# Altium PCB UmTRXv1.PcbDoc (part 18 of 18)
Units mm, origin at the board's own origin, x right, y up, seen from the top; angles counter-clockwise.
Board outline 172 x 113 mm, 6 copper layers (Top Layer, GND, MidLayer1, Mid-Layer 2, InternalPlane2, Bottom Layer); 766 components, 613 nets, 3008 pads, 1360 vias.
Unrouted connection lines stored in the file: 2.
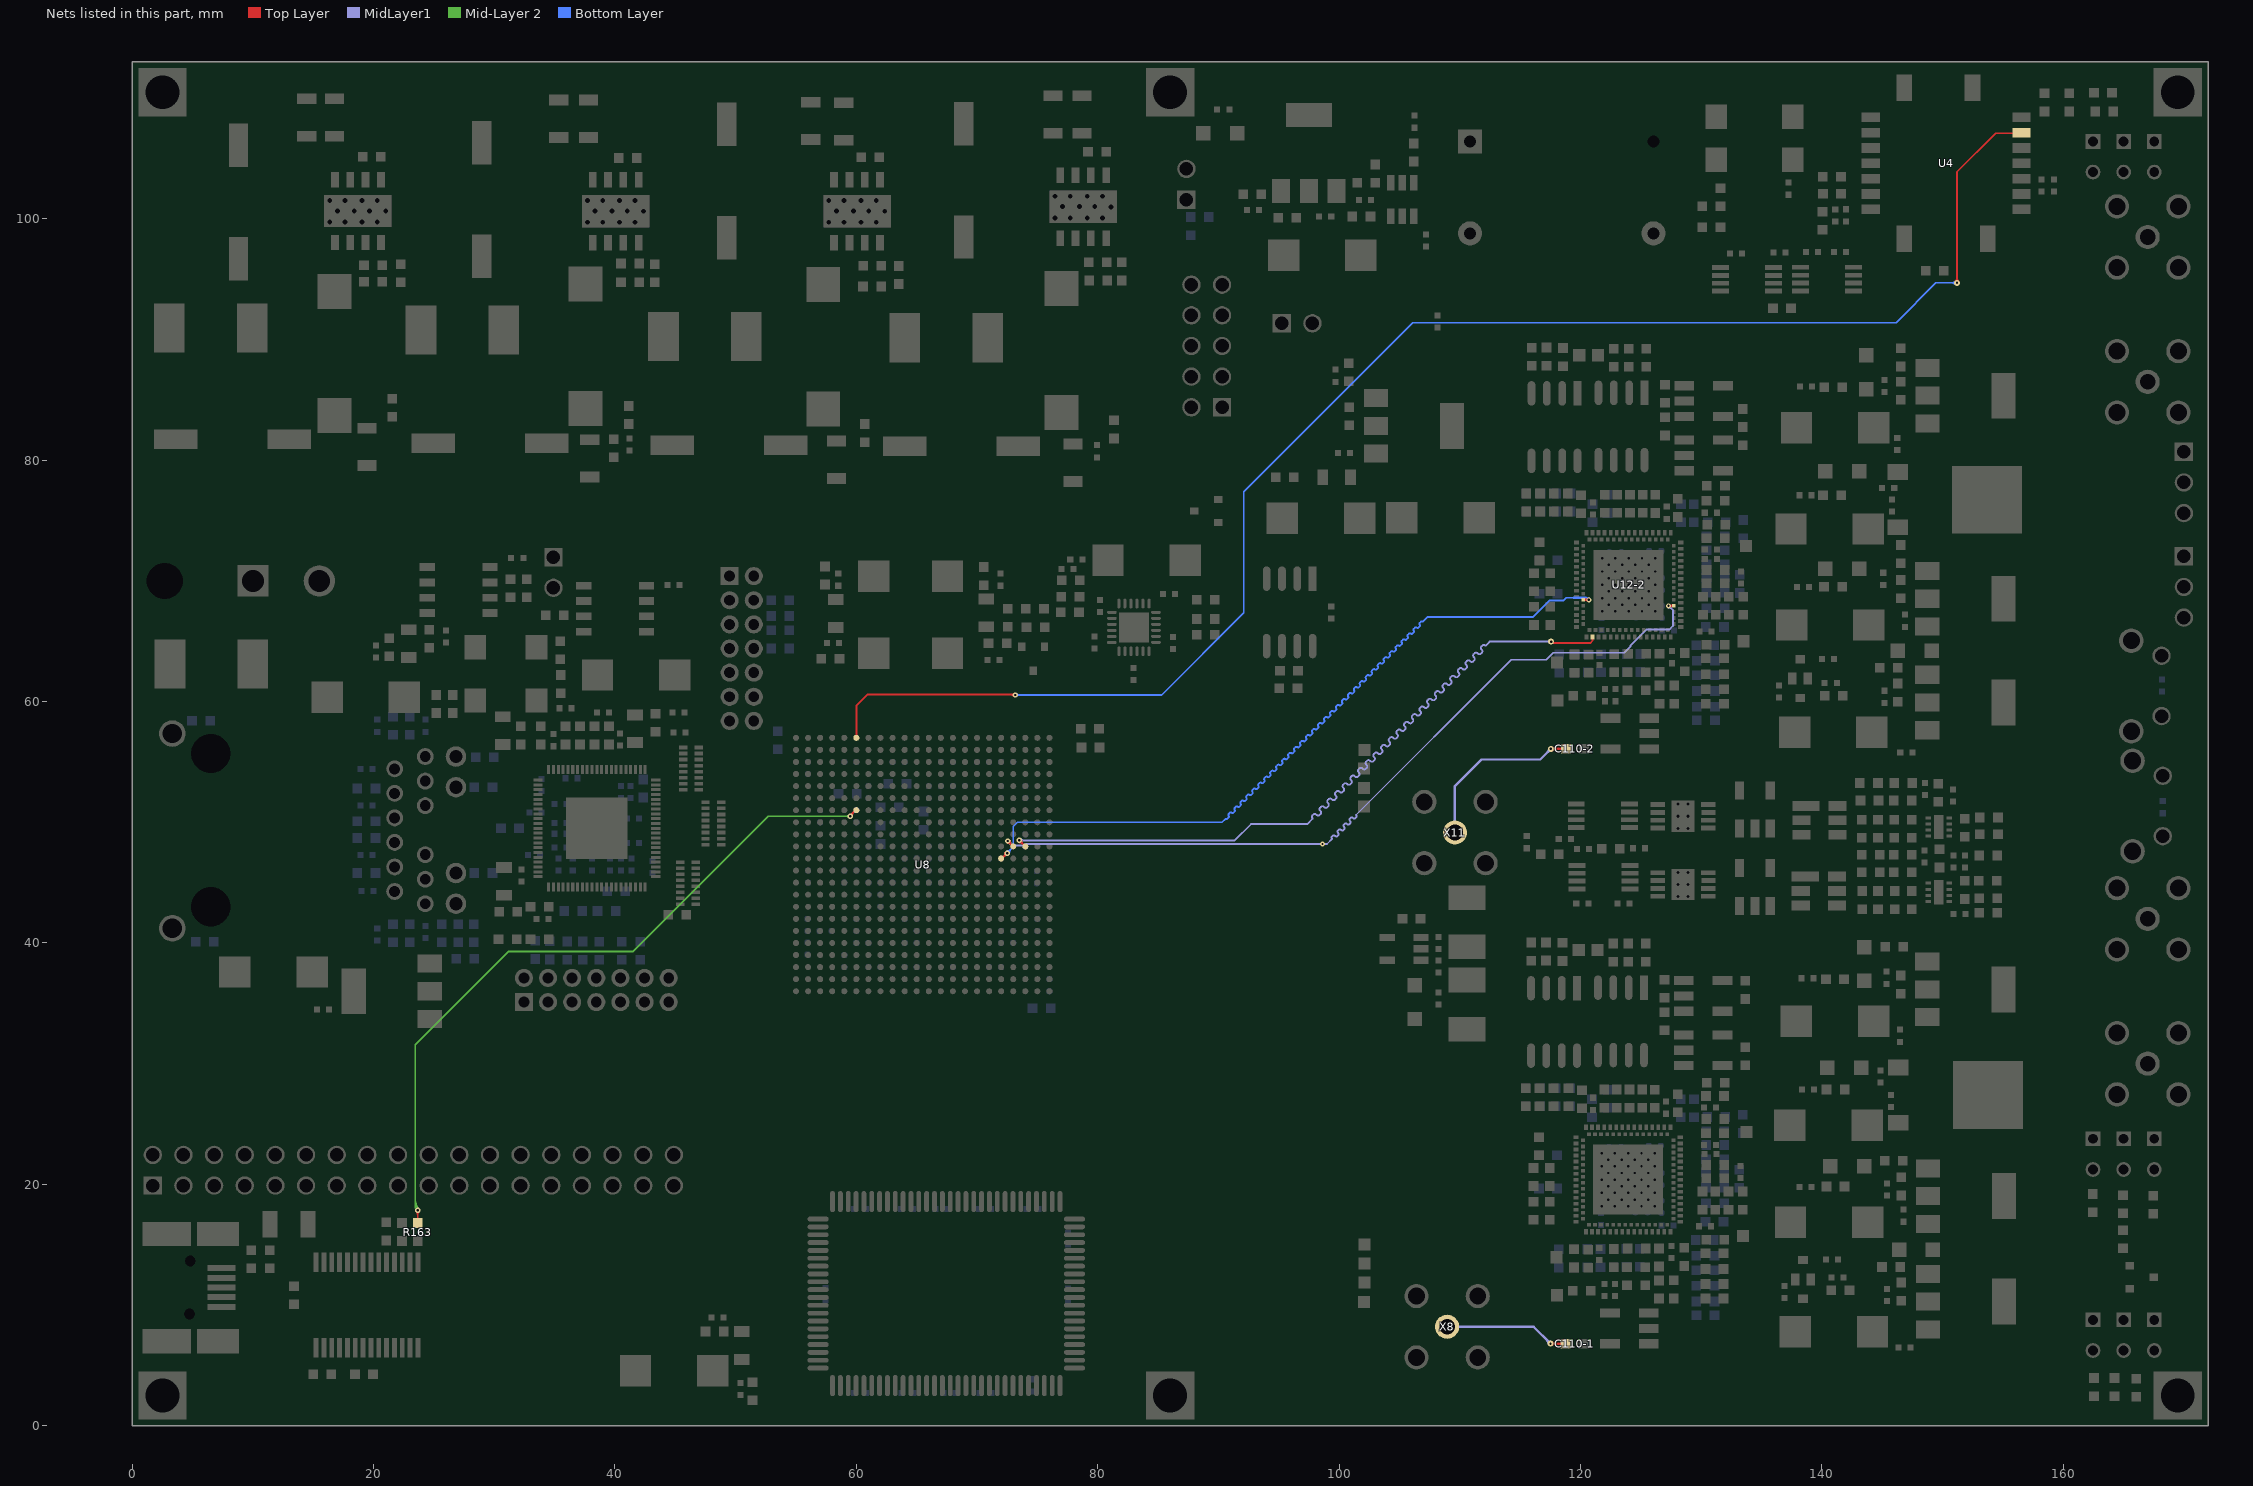
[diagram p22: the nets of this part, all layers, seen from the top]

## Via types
v1: diameter 0.45, hole 0.2, Top Layer to Bottom Layer, tented both sides, 554 vias
v2: diameter 0.5, hole 0.2, Top Layer to Bottom Layer, tented both sides, 468 vias
v3: diameter 0.7, hole 0.3, Top Layer to Bottom Layer, tented both sides, 206 vias
v4: diameter 0.4, hole 0.2, Top Layer to Bottom Layer, tented both sides, 82 vias
v5: diameter 0.8, hole 0.3, Top Layer to Bottom Layer, tented both sides, 16 vias
v6: diameter 0.6, hole 0.25, Top Layer to Bottom Layer, tented both sides, 16 vias
v7: diameter 0.5, hole 0.3, Top Layer to Bottom Layer, tented both sides, 8 vias
v8: diameter 0.7, hole 0.3, Top Layer to Bottom Layer, 4 vias
v9: diameter 0.6, hole 0.3, Top Layer to Bottom Layer, tented both sides, 4 vias
v10: diameter 0.5, hole 0.2, Top Layer to Bottom Layer, 2 vias

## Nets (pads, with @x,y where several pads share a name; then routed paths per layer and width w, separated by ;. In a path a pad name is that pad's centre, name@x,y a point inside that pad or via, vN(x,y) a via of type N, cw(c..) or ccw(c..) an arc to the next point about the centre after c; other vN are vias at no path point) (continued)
TX2D11: U8.N3 U12-2.32 | length 68.5
  Top Layer w0.15: v1@73.5,48.325 cw(c73.5,47.903) 73.799,48.201 cw(c74.098,48.5) v1@73.675,48.5 ; v1(73.5,48.5) U8.N3@74,48 ; v2(117.572,64.973) 117.584,64.973 117.707,64.85 120.8,64.85 120.996,65.046 U12-2.32@120.996,65.355
  MidLayer1 w0.15: v1(73.5,48.5) 91.35,48.5 92.7,49.85 97.35,49.85 97.795,50.295 ccw(c97.781,50.309) 97.795,50.323 cw(c97.922,50.451) 97.795,50.578 97.859,50.641 cw(c97.986,50.514) 98.113,50.641 98.127,50.627 98.141,50.613 ccw(c98.269,50.74) 98.396,50.613 98.46,50.677 ccw(c98.332,50.804) 98.46,50.931 98.445,50.945 98.431,50.96 cw(c98.559,51.087) 98.431,51.214 98.495,51.278 cw(c98.622,51.151) 98.75,51.278 98.764,51.264 98.778,51.25 ccw(c98.905,51.377) 99.032,51.25 99.096,51.313 ccw(c98.969,51.44) 99.096,51.568 99.082,51.582 99.068,51.596 cw(c99.195,51.723) 99.068,51.851 99.131,51.914 cw(c99.259,51.787) 99.386,51.914 99.4,51.9 99.414,51.886 ccw(c99.542,52.013) 99.669,51.886 99.732,51.95 ccw(c99.605,52.077) 99.732,52.204 99.718,52.218 99.704,52.232 cw(c99.831,52.36) 99.704,52.487 99.768,52.551 cw(c99.895,52.423) 100.022,52.551 100.036,52.536 100.051,52.522 ccw(c100.178,52.65) 100.305,52.522 100.369,52.586 ccw(c100.242,52.713) 100.369,52.841 100.355,52.855 100.341,52.869 cw(c100.468,52.996) 100.341,53.123 100.404,53.187 cw(c100.531,53.06) 100.659,53.187 100.673,53.173 100.687,53.159 ccw(c100.814,53.286) 100.942,53.159 101.005,53.222 ccw(c100.878,53.35) 101.005,53.477 100.991,53.491 100.977,53.505 cw(c101.104,53.632) 100.977,53.76 101.041,53.823 cw(c101.168,53.696) 101.295,53.823 101.309,53.809 101.323,53.795 ccw(c101.451,53.922) 101.578,53.795 101.642,53.859 ccw(c101.514,53.986) 101.642,54.113 101.627,54.127 101.613,54.142 cw(c101.741,54.269) 101.613,54.396 101.677,54.46 cw(c101.804,54.333) 101.932,54.46 101.946,54.446 101.96,54.432 ccw(c102.087,54.559) 102.214,54.432 102.278,54.495 ccw(c102.151,54.622) 102.278,54.75 102.264,54.764 102.25,54.778 cw(c102.377,54.905) 102.25,55.033 102.313,55.096 cw(c102.441,54.969) 102.568,55.096 102.582,55.082 102.596,55.068 ccw(c102.723,55.195) 102.851,55.068 102.914,55.132 ccw(c102.787,55.259) 102.914,55.386 102.9,55.4 102.886,55.414 cw(c103.013,55.542) 102.886,55.669 102.95,55.733 cw(c103.077,55.605) 103.204,55.733 103.218,55.718 103.233,55.704 ccw(c103.36,55.832) 103.487,55.704 103.551,55.768 ccw(c103.424,55.895) 103.551,56.023 103.537,56.037 103.523,56.051 cw(c103.65,56.178) 103.523,56.305 103.586,56.369 cw(c103.713,56.242) 103.841,56.369 103.855,56.355 103.869,56.341 ccw(c103.996,56.468) 104.124,56.341 104.187,56.404 ccw(c104.06,56.532) 104.187,56.659 104.173,56.673 104.159,56.687 cw(c104.286,56.814) 104.159,56.942 104.223,57.005 cw(c104.35,56.878) 104.477,57.005 104.491,56.991 104.505,56.977 ccw(c104.633,57.104) 104.76,56.977 104.824,57.041 ccw(c104.696,57.168) 104.824,57.295 104.809,57.309 104.795,57.324 cw(c104.923,57.451) 104.795,57.578 104.859,57.642 cw(c104.986,57.515) 105.113,57.642 105.128,57.628 105.142,57.613 ccw(c105.269,57.741) 105.396,57.613 105.46,57.677 ccw(c105.333,57.804) 105.46,57.932 105.446,57.946 105.432,57.96 cw(c105.559,58.087) 105.432,58.215 105.495,58.278 cw(c105.623,58.151) 105.75,58.278 105.764,58.264 105.778,58.25 ccw(c105.905,58.377) 106.033,58.25 106.096,58.314 ccw(c105.969,58.441) 106.096,58.568 106.082,58.582 106.068,58.596 cw(c106.195,58.724) 106.068,58.851 106.132,58.915 cw(c106.259,58.787) 106.386,58.915 106.4,58.9 106.415,58.886 ccw(c106.542,59.014) 106.669,58.886 106.733,58.95 ccw(c106.605,59.077) 106.733,59.204 106.704,59.233 cw(c106.832,59.36) 106.704,59.487 106.768,59.551 cw(c106.895,59.424) 107.023,59.551 107.037,59.537 107.051,59.523 ccw(c107.178,59.65) 107.306,59.523 107.369,59.586 ccw(c107.242,59.714) 107.369,59.841 107.355,59.855 107.341,59.869 cw(c107.468,59.996) 107.341,60.124 107.405,60.187 cw(c107.532,60.06) 107.659,60.187 107.673,60.173 107.687,60.159 ccw(c107.815,60.286) 107.942,60.159 108.006,60.223 ccw(c107.878,60.35) 108.006,60.477 107.991,60.491 107.977,60.506 cw(c108.105,60.633) 107.977,60.76 108.041,60.824 cw(c108.168,60.696) 108.295,60.824 108.31,60.81 108.324,60.795 ccw(c108.451,60.923) 108.578,60.795 108.642,60.859 ccw(c108.515,60.986) 108.642,61.114 108.628,61.128 108.614,61.142 cw(c108.741,61.269) 108.614,61.397 108.677,61.46 cw(c108.805,61.333) 108.932,61.46 108.96,61.432 ccw(c109.087,61.559) 109.215,61.432 109.278,61.496 ccw(c109.151,61.623) 109.278,61.75 109.264,61.764 109.25,61.778 cw(c109.377,61.906) 109.25,62.033 109.314,62.097 cw(c109.441,61.969) 109.568,62.097 109.582,62.082 109.597,62.068 ccw(c109.724,62.196) 109.851,62.068 109.915,62.132 ccw(c109.787,62.259) 109.915,62.386 109.901,62.401 109.886,62.415 cw(c110.014,62.542) 109.886,62.669 109.95,62.733 cw(c110.077,62.606) 110.205,62.733 110.219,62.719 110.233,62.705 ccw(c110.36,62.832) 110.488,62.705 110.551,62.768 ccw(c110.424,62.896) 110.551,63.023 110.537,63.037 110.523,63.051 cw(c110.65,63.178) 110.523,63.306 110.586,63.369 cw(c110.714,63.242) 110.841,63.369 110.855,63.355 110.869,63.341 ccw(c110.997,63.468) 111.124,63.341 111.188,63.405 ccw(c111.06,63.532) 111.188,63.659 111.159,63.688 cw(c111.287,63.815) 111.159,63.942 111.223,64.006 cw(c111.35,63.878) 111.477,64.006 111.492,63.992 111.506,63.977 ccw(c111.633,64.105) 111.76,63.977 111.824,64.041 ccw(c111.697,64.168) 111.824,64.296 111.81,64.31 111.796,64.324 cw(c111.923,64.451) 111.796,64.578 111.859,64.642 cw(c111.987,64.515) 112.114,64.642 ccw(c112.128,64.656) 112.142,64.642 112.473,64.973 v2(117.572,64.973) ; v1@73.624,48.376 cw(c73.922,48.078) 73.922,48.5 cw(c73.922,48.922) v1@73.624,48.624 ; v2@117.448,64.85 ccw(c117.149,64.551) 117.149,64.973 ccw(c117.149,65.396) v2@117.448,65.097
TX2EN: U8.N4 U12-2.66 | length 69.4
  Top Layer w0.15: v1@72.55,48.275 cw(c72.55,47.853) 72.849,48.151 cw(c73.147,48.45) v1@72.725,48.45 ; v1(72.55,48.45) U8.N4@73,48
  Top Layer w0.2: v4@127.321,67.93 U12-2.66@127.746,67.93 ; v4@127.367,67.859 cw(c127.537,67.688) 127.537,67.93 cw(c127.537,68.171) v4@127.367,68.001
  MidLayer1 w0.15: v1@72.55,48.275 cw(c72.55,47.853) 72.849,48.151 cw(c73.147,48.45) v1@72.725,48.45 ; v1(72.55,48.45) 72.925,48.075 73.921,48.075 74.046,48.2 v1(98.625,48.2) 99,48.2 99.424,48.624 99.417,48.631 cw(c99.516,48.73) 99.417,48.829 99.466,48.878 cw(c99.565,48.779) 99.664,48.878 99.671,48.871 99.678,48.864 ccw(c99.777,48.963) 99.876,48.864 99.926,48.914 ccw(c99.827,49.013) 99.926,49.112 99.919,49.119 99.912,49.126 cw(c100.011,49.225) 99.912,49.324 99.961,49.373 cw(c100.06,49.274) 100.159,49.373 100.166,49.366 100.173,49.359 ccw(c100.272,49.458) 100.371,49.359 100.421,49.409 ccw(c100.322,49.508) 100.421,49.607 100.414,49.614 100.407,49.621 cw(c100.506,49.72) 100.407,49.819 100.456,49.868 cw(c100.555,49.769) 100.654,49.868 100.661,49.861 100.668,49.854 ccw(c100.767,49.953) 100.866,49.854 100.916,49.904 ccw(c100.817,50.003) 100.916,50.102 100.909,50.109 100.902,50.116 cw(c101.001,50.215) 100.902,50.314 100.951,50.363 cw(c101.05,50.264) 101.149,50.363 101.163,50.349 ccw(c101.262,50.448) 101.361,50.349 101.411,50.399 ccw(c101.312,50.498) 101.411,50.597 101.404,50.604 114.265,63.465 117.15,63.465 117.733,64.048 119.176,64.048 119.177,64.05 119.923,64.05 119.924,64.048 123.614,64.048 124.15,64.584 124.15,64.673 125.444,65.967 127.363,65.967 127.671,66.275 127.671,67.585 127.326,67.93 v4(127.296,67.93) ; v4@127.296,67.805 cw(c127.296,67.43) 127.561,67.695 ; v4@127.421,67.93 ccw(c127.65,67.93) 127.488,67.768
TX2IQSEL: U8.M5 U12-2.20 | length 68.6
  Top Layer w0.15: U8.M5@72,47 72.05,47 v1(72.5,47.45) ; v1@72.325,47.45 cw(c71.903,47.45) 72.201,47.151 cw(c72.5,46.853) v1@72.5,47.275
  Top Layer w0.2: U12-2.20@120.246,68.43 v4@120.671,68.43 ; v4@120.625,68.359 ccw(c120.455,68.188) 120.455,68.43 ccw(c120.455,68.671) v4@120.625,68.501
  Bottom Layer w0.15: v1(72.5,47.45) 73,47.95 73,49.65 73.35,50 90.3,50 90.595,50.295 ccw(c90.665,50.365) 90.736,50.295 90.842,50.401 ccw(c90.771,50.471) 90.842,50.542 cw(c90.913,50.613) 90.842,50.684 90.948,50.79 cw(c91.019,50.719) 91.09,50.79 ccw(c91.16,50.86) 91.231,50.79 91.337,50.896 ccw(c91.266,50.966) 91.337,51.037 cw(c91.408,51.108) 91.337,51.179 91.443,51.285 cw(c91.514,51.214) 91.585,51.285 ccw(c91.655,51.355) 91.726,51.285 91.832,51.391 ccw(c91.761,51.461) 91.832,51.532 cw(c91.903,51.603) 91.832,51.673 91.938,51.78 cw(c92.009,51.709) 92.08,51.78 ccw(c92.15,51.85) 92.221,51.78 92.327,51.886 ccw(c92.256,51.956) 92.327,52.027 cw(c92.398,52.098) 92.327,52.168 92.433,52.275 cw(c92.504,52.204) 92.575,52.275 ccw(c92.645,52.345) 92.716,52.275 92.822,52.381 ccw(c92.751,52.451) 92.822,52.522 cw(c92.893,52.593) 92.822,52.663 92.928,52.77 cw(c92.999,52.699) 93.07,52.77 ccw(c93.14,52.84) 93.211,52.769 93.317,52.876 ccw(c93.246,52.946) 93.317,53.017 cw(c93.388,53.088) 93.317,53.158 93.423,53.264 cw(c93.494,53.194) 93.564,53.264 ccw(c93.635,53.335) 93.706,53.264 93.812,53.371 ccw(c93.741,53.441) 93.812,53.512 cw(c93.883,53.583) 93.812,53.653 93.918,53.759 ; v1@72.5,47.625 ccw(c72.5,48.047) 72.799,47.749 ccw(c73.097,47.45) v1@72.675,47.45 ; 93.918,53.759 cw(c93.989,53.689) 94.059,53.759 ccw(c94.13,53.83) 94.201,53.759 94.307,53.866 ccw(c94.236,53.936) 94.307,54.007 cw(c94.378,54.078) 94.307,54.148 94.413,54.254 cw(c94.484,54.184) 94.554,54.254 ccw(c94.625,54.325) 94.696,54.254 94.802,54.36 ccw(c94.731,54.431) 94.802,54.502 cw(c94.873,54.573) 94.802,54.643 94.908,54.749 cw(c94.979,54.679) 95.049,54.749 ccw(c95.12,54.82) 95.191,54.749 ; 95.191,54.749 95.297,54.855 ; 95.297,54.855 ccw(c95.226,54.926) 95.297,54.997 cw(c95.368,55.068) 95.297,55.138 95.403,55.244 cw(c95.474,55.174) 95.544,55.244 ccw(c95.615,55.315) 95.686,55.244 95.792,55.35 ccw(c95.721,55.421) 95.792,55.492 cw(c95.863,55.563) 95.792,55.633 95.898,55.739 cw(c95.969,55.669) 96.039,55.739 ccw(c96.11,55.81) 96.181,55.739 96.287,55.845 ccw(c96.216,55.916) 96.287,55.987 cw(c96.358,56.058) 96.287,56.128 ; 96.287,56.128 96.393,56.234 cw(c96.464,56.164) 96.534,56.234 ccw(c96.605,56.305) 96.676,56.234 96.782,56.34 ccw(c96.711,56.411) 96.782,56.482 cw(c96.853,56.553) 96.782,56.623 96.888,56.729 cw(c96.959,56.659) 97.029,56.729 ccw(c97.1,56.8) 97.171,56.729 97.277,56.835 ccw(c97.206,56.906) 97.277,56.977 cw(c97.347,57.047) 97.277,57.118 97.383,57.224 cw(c97.454,57.154) 97.524,57.224 ccw(c97.595,57.295) 97.666,57.224 97.772,57.33 ccw(c97.701,57.401) 97.772,57.472 cw(c97.842,57.542) 97.772,57.613 97.878,57.719 cw(c97.949,57.649) 98.019,57.719 ccw(c98.09,57.79) 98.161,57.719 98.267,57.825 ccw(c98.196,57.896) 98.267,57.967 cw(c98.337,58.037) 98.267,58.108 98.373,58.214 cw(c98.444,58.144) 98.514,58.214 ccw(c98.585,58.285) 98.656,58.214 98.762,58.32 ccw(c98.691,58.391) 98.762,58.462 cw(c98.832,58.532) 98.762,58.603 98.868,58.709 cw(c98.938,58.638) 99.009,58.709 ccw(c99.08,58.78) 99.151,58.709 99.257,58.815 ccw(c99.186,58.886) 99.257,58.957 cw(c99.327,59.027) 99.257,59.098 99.363,59.204 cw(c99.433,59.133) 99.504,59.204 ccw(c99.575,59.275) 99.646,59.204 99.752,59.31 ccw(c99.681,59.381) 99.752,59.452 cw(c99.822,59.522) 99.752,59.593 99.858,59.699 cw(c99.928,59.628) 99.999,59.699 ccw(c100.07,59.77) 100.141,59.699 100.247,59.805 ccw(c100.176,59.876) 100.247,59.947 cw(c100.317,60.017) 100.247,60.088 100.353,60.194 cw(c100.423,60.123) 100.494,60.194 ccw(c100.565,60.265) 100.636,60.194 100.742,60.3 ccw(c100.671,60.371) 100.742,60.442 cw(c100.812,60.512) 100.742,60.583 100.848,60.689 cw(c100.918,60.618) 100.989,60.689 ccw(c101.06,60.76) 101.13,60.689 101.237,60.795 ccw(c101.166,60.866) 101.237,60.937 cw(c101.307,61.007) 101.237,61.078 101.343,61.184 cw(c101.413,61.113) 101.484,61.184 ccw(c101.555,61.255) 101.625,61.184 101.732,61.29 ccw(c101.661,61.361) 101.732,61.432 cw(c101.802,61.502) 101.732,61.573 101.838,61.679 cw(c101.908,61.608) 101.979,61.679 ccw(c102.05,61.75) 102.12,61.679 102.227,61.785 ccw(c102.156,61.856) 102.227,61.927 cw(c102.297,61.997) 102.226,62.068 102.333,62.174 cw(c102.403,62.103) 102.474,62.174 ccw(c102.545,62.245) 102.615,62.174 102.721,62.28 ccw(c102.651,62.351) 102.721,62.421 cw(c102.792,62.492) 102.721,62.563 102.828,62.669 cw(c102.898,62.598) 102.969,62.669 ccw(c103.04,62.74) 103.11,62.669 103.216,62.775 ccw(c103.146,62.846) 103.216,62.916 cw(c103.287,62.987) 103.216,63.058 103.323,63.164 cw(c103.393,63.093) 103.464,63.164 ccw(c103.535,63.235) 103.605,63.164 103.711,63.27 ccw(c103.641,63.341) 103.711,63.411 cw(c103.782,63.482) 103.711,63.553 103.818,63.659 cw(c103.888,63.588) 103.959,63.659 ccw(c104.03,63.73) 104.1,63.659 104.206,63.765 ccw(c104.136,63.836) 104.206,63.906 cw(c104.277,63.977) 104.206,64.048 104.312,64.154 cw(c104.383,64.083) 104.454,64.154 ccw(c104.525,64.225) 104.595,64.154 104.701,64.26 ccw(c104.631,64.331) 104.701,64.401 cw(c104.772,64.472) 104.701,64.543 104.807,64.649 cw(c104.878,64.578) 104.949,64.649 ccw(c105.02,64.72) 105.09,64.649 105.196,64.755 ccw(c105.126,64.826) 105.196,64.896 cw(c105.267,64.967) 105.196,65.038 105.302,65.144 cw(c105.373,65.073) 105.444,65.144 ccw(c105.515,65.215) 105.585,65.144 105.691,65.25 ccw(c105.621,65.321) 105.691,65.391 cw(c105.762,65.462) 105.691,65.533 105.797,65.639 cw(c105.868,65.568) 105.939,65.639 ccw(c106.01,65.71) 106.08,65.639 106.186,65.745 ccw(c106.116,65.816) 106.186,65.886 cw(c106.257,65.957) 106.186,66.028 106.292,66.134 cw(c106.363,66.063) 106.434,66.134 ccw(c106.505,66.205) 106.575,66.134 106.681,66.24 ccw(c106.611,66.311) 106.681,66.381 cw(c106.752,66.452) 106.681,66.523 106.787,66.629 cw(c106.858,66.558) 106.929,66.629 107.3,67 116.05,67 117.425,68.375 118.572,68.375 118.809,68.612 119.45,68.612
  Bottom Layer w0.2: 119.45,68.612 120.448,68.612 ; v4@120.685,68.529 cw(c120.652,68.816) 120.448,68.612 ; v4(120.696,68.43) 120.63,68.43 120.448,68.612
TX-1: C110-1.2 X8.1 | length 11.5
  Top Layer w0.2: v2(117.515,6.798) 117.525,6.788 C110-1.2@118.757,6.788 ; v2@117.621,6.692 cw(c117.852,6.461) 117.852,6.788 ; v2@117.621,6.904 ccw(c117.902,7.185) 117.902,6.788
  MidLayer1 w0.2: X8.1@108.95,8.2 116.113,8.2 v2(117.515,6.798) ; v2@117.365,6.798 ccw(c117.002,6.798) 117.258,7.054 ccw(c117.515,7.31) v2@117.515,6.948
TX-2: C110-2.2 X11.1 | length 15.5
  Top Layer w0.2: v2(117.554,56.09) v2@117.568,56.09 ; v2@117.564,56.08 C110-2.2@118.796,56.08 ; v2@117.66,55.984 cw(c117.891,55.753) 117.891,56.08 ; v2@117.66,56.196 ccw(c117.941,56.477) 117.941,56.08
  MidLayer1 w0.2: X11.1@109.6,49.15 109.6,53 111.8,55.2 116.664,55.2 v2(117.554,56.09) ; v2@117.404,56.09 cw(c117.041,56.09) 117.297,55.834 cw(c117.554,55.578) v2@117.554,55.94
TXD1: R163.1 U8.T17 | length 62.4
  Top Layer w0.15: v1@23.544,17.744 cw(c23.288,17.488) 23.65,17.488 cw(c24.012,17.488) v1@23.756,17.744 ; R163.1@23.65,16.8 v1(23.65,17.85) ; v1(59.5,50.5) 59.5,50.6 U8.T17@59.95,51.05 ; v1@59.65,50.5 cw(c60.254,50.5) U8.T17@59.827,50.927
  Mid-Layer 2 w0.15: 23.45,18.333 ccw(c24.133,18.333) v1(23.65,17.85) 23.45,18.05 23.45,31.55 31.2,39.3 41.5,39.3 52.7,50.5 v1(59.5,50.5) ; 23.45,18.695 ccw(c24.495,18.695) v1@23.756,17.956 ; v1@59.394,50.394 ccw(c59.138,50.138) 59.138,50.5 ccw(c59.138,50.862) v1@59.394,50.606
TXD2: U4.6 U8.AB17 | length 132.6
  Top Layer w0.15: U8.AB17@60,57 60,59.65 60.95,60.6 73.1,60.6 v1(73.15,60.55) ; 72.667,60.6 cw(c72.667,60.067) v1@73.044,60.444 ; 72.909,60.6 ccw(c72.909,60.791) v1@73.044,60.656 ; v2@151.076,94.824 ccw(c150.778,95.122) 151.2,95.122 ccw(c151.622,95.122) v2@151.324,94.824 ; v2(151.2,94.7) 151.2,103.9 154.4,107.1 U4.6@156.55,107.1
  Bottom Layer w0.15: v1(73.15,60.55) 85.3,60.55 92.1,67.35 92.1,77.4 106.1,91.4 146.15,91.4 149.45,94.7 v2(151.2,94.7) ; v1@73.256,60.444 cw(c73.512,60.188) 73.512,60.55 cw(c73.512,60.912) v1@73.256,60.656 ; v2@151.076,94.576 ccw(c150.778,94.278) 150.778,94.7 ccw(c150.778,95.122) v2@151.076,94.824
pads on no net: SW1.3 SW1.4 SW2.3 SW2.4 T1-1.2 T1-2.2 T2-1.2 T2-2.2 U4.10 U4.11 U4.12 U4.13 U4.14 U5.1 U8.AA4 U8.AA6 U8.AA8 U8.AA10 U8.AA12 U8.AA21 U8.AB3 U8.AB5 U8.AB15 U8.AB16 U8.AB21 U8.E8 U8.E10 U8.F8 U8.F9 U8.F10 U8.F12 U8.G8 U8.G9 U8.G11 U8.G17 U8.H10 U8.H11 U8.H12 U8.H17 U8.M6 U8.M16 U8.M17 U8.M18 U8.M21 U8.P7 U8.P17 U8.P18 U8.P19 U8.P21 U8.P22 U8.R4 U8.R7 U8.R8 U8.R9 U8.R11 U8.R13 U8.R15 U8.R16 U8.R19 U8.T7 U8.T8 U8.T10 U8.T11 U8.T12 U8.T14 U8.T15 U8.T16 U8.T20 U8.U6 U8.U8 U8.U9 U8.U10 U8.U12 U8.U13 U8.U14 U8.U16 U8.U17 U8.U19 U8.V5 U8.V7 U8.V9 U8.V11 U8.V13 U8.V15 U8.V17 U8.V18 U8.V19 U8.V20 U8.W6 U8.W8 U8.W9 U8.W10 U8.W11 U8.W13 U8.W14 U8.W15 U8.W17 U8.W18 U8.Y5 U8.Y6 U8.Y7 U8.Y8 U8.Y9 U8.Y10 U8.Y11 U8.Y12 U8.Y13 U8.Y14 U8.Y16 U8.Y18 U8.Y20 U9.5 U9.7 U9.8 U9.9 U9.10 U9.11 U9.12 U9.14 U9.15 U9.23 U9.40 U9.41 U9.42 U9.43 U9.46 U11.14 U11.16 U11.38 U11.39 U11.66 U12-1.48 U12-1.50 U12-1.91 U12-1.92 U12-1.94 U12-1.95 U12-1.103 U12-1.104 U12-1.105 U12-1.106 U12-2.48 U12-2.50 U12-2.91 U12-2.92 U12-2.94 U12-2.95 U12-2.103 U12-2.104 U12-2.105 U12-2.106 U15. U15.6 U16. U16.6 U17. U17.6 U24. U24.3 U24.4 U24.5 U24.6 U24.8 U25. U25.3 U25.4 U25.5 U25.6 U25.8 U33.6 U33.8 U33.10 U33.12 U33.13 U33.14 U33.19 U33.22 U33.23 U33.24 U33.27 U33.28 U34. U34.6 X1.12 X1.14 X2.12 X2.14 X3.MH1 X3.MH2 X3.x X4.0 X5.0

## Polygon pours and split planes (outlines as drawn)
+3,3VFPGA on MidLayer1 "Mid1+3.3V_FPGA" (solid, remove dead copper, pour order 7): 28.9,71.75 30.4,73.25 50.7,73.25 56.95,67 77.25,67.05 78.25,65.95 78.3,63.05 79.8,61.45 81.8,59.25 81.75,54.95 78.295,52.25 70.925,46.275 70.95,39.55 69.109,38.15 49.8,38.15 49.4,33.1 29.6,33.1 28.9,33.8
GND on MidLayer1 "Mid1_GND" (solid, remove dead copper, pour order 10): -1,-2 174,-2 174,115 0,115 -2,115
NetC214_2 on Mid-Layer 2 "Top" (solid, remove dead copper, pour order 8): 33.45,59.5 38.45,59.5 41.75,56.2 43.3,54.65 43.3,49.45 43.3,45.2 42.55,44.45 42.2,44.1 35.75,44.1 34.75,44.1 33.8,45.05 32.25,46.6 32.25,57.95 32.25,58.25 33.5,59.5
GND on Mid-Layer 2 "Mid1_GND" (solid, remove dead copper, pour order 9): -1,-2 174,-2 174,115 0,115 -2,115
GND on GND (split plane): 171.699,0.301 0.301,0.301 0.301,112.699 171.699,112.699
+1,8VALMS-2 on InternalPlane2 (split plane): 158.199,89.187 158.199,81.001 148.45,81.001 148.411,80.996 148.385,80.985 148.374,80.981 148.343,80.957 148.002,80.616 131.825,80.616 131.825,87.463 134.075,89.712 157.674,89.712
+1,8VDLMS-2 on InternalPlane2 (split plane): 133.149,73.882 133.149,72.613 133.074,72.538 132.389,72.538 132.349,72.533 132.313,72.518 132.282,72.494 132.022,72.234 131.998,72.203 131.983,72.166 131.977,72.127 131.977,70.921 131.983,70.882 131.998,70.846 132.022,70.814 132.493,70.343 132.524,70.319 132.561,70.304 132.6,70.299 135.35,70.299 135.389,70.304 135.426,70.319 135.457,70.343 137.277,72.163 150.114,72.163 150.153,72.168 150.175,72.177 150.19,72.183 150.221,72.207 150.413,72.399 158.199,72.399 158.199,64.001 145.51,64.001 145.48,64.024 145.444,64.039 145.404,64.044 144.401,64.044 144.239,64.207 144.208,64.231 144.192,64.237 144.171,64.246 144.132,64.251 136.958,64.251 136.958,64.306 136.958,65.108 136.953,65.147 136.938,65.184 136.914,65.215 135.172,66.957 135.14,66.981 135.125,66.987 135.104,66.996 135.065,67.001 133.6,67.001 133.561,66.996 133.524,66.981 133.493,66.957 132.824,66.288 132.8,66.257 132.785,66.221 132.78,66.181 132.78,65.569 132.78,65.132 130.412,62.764 128.808,62.764 128.769,62.759 128.733,62.744 128.701,62.72 126.933,60.952 122.73,60.952 122.691,60.947 122.654,60.932 122.623,60.907 121.129,59.414 117.633,59.414 117.619,59.447 117.595,59.478 116.73,60.343 116.73,61.942 118.86,64.071 119.772,64.071 119.774,64.069 119.811,64.054 119.85,64.049 119.889,64.054 119.926,64.069 119.928,64.071 127.408,64.071 127.447,64.076 127.483,64.091 127.515,64.115 128.251,64.852 128.275,64.883 128.29,64.919 128.295,64.959 128.295,73.581 129.202,74.488 132.542,74.488
+2,5VLMS-2 on InternalPlane2 (split plane): 144.232,63.786 144.263,63.762 144.3,63.747 144.339,63.742 145.364,63.742 145.394,63.719 145.43,63.704 145.469,63.699 158.199,63.699 158.199,56.313 157.229,55.343 136.164,55.343 136.164,62.623 136.914,63.373 136.938,63.404 136.953,63.441 136.958,63.48 136.958,63.949 144.069,63.949
+3,3VLMS-2 on InternalPlane2 (split plane): 158.199,72.701 150.35,72.701 150.311,72.696 150.274,72.681 150.243,72.657 150.052,72.466 137.214,72.466 137.175,72.46 137.139,72.445 137.107,72.421 135.287,70.601 132.663,70.601 132.28,70.984 132.28,72.064 132.451,72.236 133.137,72.236 133.176,72.241 133.197,72.25 133.212,72.256 133.244,72.28 133.407,72.443 133.431,72.474 133.446,72.511 133.451,72.55 133.451,73.944 133.446,73.983 133.437,74.005 133.431,74.02 133.407,74.051 132.712,74.746 132.681,74.77 132.644,74.785 132.605,74.79 129.139,74.79 129.1,74.785 129.079,74.776 129.063,74.77 129.032,74.746 128.081,73.795 120.319,73.795 120.28,73.79 120.258,73.781 120.243,73.775 120.212,73.751 119.743,73.282 119.719,73.251 119.704,73.214 119.699,73.175 119.699,64.374 118.797,64.374 118.758,64.368 118.722,64.353 118.69,64.329 116.472,62.111 116.448,62.08 116.433,62.043 116.428,62.004 116.428,60.28 116.433,60.241 116.448,60.205 116.472,60.173 117.362,59.284 117.359,59.263 117.364,59.224 117.379,59.187 117.403,59.156 117.435,59.132 117.471,59.117 117.51,59.112 121.192,59.112 121.231,59.117 121.268,59.132 121.299,59.156 122.792,60.649 126.996,60.649 127.035,60.654 127.072,60.669 127.103,60.694 128.871,62.461 130.475,62.461 130.514,62.467 130.551,62.482 130.582,62.506 133.038,64.962 133.063,64.994 133.078,65.03 133.083,65.069 133.083,65.569 133.083,66.119 133.663,66.699 135.002,66.699 136.655,65.045 136.655,64.306 136.655,64.1 136.655,63.542 135.906,62.793 135.882,62.761 135.866,62.725 135.861,62.686 135.861,55.343 115.884,55.343 115.02,56.207 115.02,72.692 122.641,80.313 148.065,80.313 148.104,80.319 148.125,80.327 148.14,80.334 148.172,80.358 148.513,80.699 158.199,80.699
GND on InternalPlane2 (split plane): 127.993,65.021 127.345,64.374 120.001,64.374 120.001,73.112 120.382,73.493 127.993,73.493
+1,8VALMS-1 on InternalPlane2 (split plane): 157.749,39.737 157.749,31.801 144.673,31.801 144.634,31.796 144.597,31.781 144.566,31.757 144.133,31.324 131.786,31.324 131.786,38.171 134.036,40.421 157.065,40.421
+1,8VDLMS-1 on InternalPlane2 (split plane): 133.304,24.396 134.784,22.915 134.815,22.891 134.852,22.876 134.891,22.871 143.578,22.871 143.618,22.876 143.639,22.885 143.654,22.891 143.685,22.915 143.869,23.099 157.749,23.099 157.749,14.651 146.513,14.651 145.907,15.257 145.876,15.281 145.839,15.296 145.8,15.301 132.265,15.301 132.226,15.296 132.189,15.281 132.158,15.257 130.373,13.472 128.769,13.472 128.73,13.467 128.694,13.452 128.662,13.428 126.894,11.66 122.691,11.66 122.652,11.655 122.615,11.64 122.584,11.616 121.09,10.122 117.594,10.122 117.58,10.155 117.556,10.186 116.692,11.051 116.692,13.092 118.379,14.779 127.369,14.779 127.408,14.784 127.444,14.799 127.476,14.823 128.212,15.56 128.236,15.591 128.251,15.628 128.256,15.667 128.256,22.967 128.881,23.592 128.882,23.593 128.883,23.594 130.485,25.196 132.503,25.196
GND on InternalPlane2 (split plane): 128.561,23.7 127.998,23.137 127.974,23.106 127.959,23.069 127.954,23.03 127.954,15.729 127.306,15.082 119.701,15.082 119.701,23.487 120.713,24.499 127.762,24.499
+2,5VLMS-1 on InternalPlane2 (split plane): 146.343,14.393 146.374,14.369 146.411,14.354 146.45,14.349 157.749,14.349 157.749,6.713 157.087,6.051 136.125,6.051 136.125,13.394 136.125,14.999 145.737,14.999
+1,2VFPGA on InternalPlane2 (split plane): 66.399,69.337 66.399,56.713 65.943,56.257 65.919,56.226 65.904,56.189 65.899,56.15 65.899,55.3 65.904,55.261 65.919,55.224 65.943,55.193 67.949,53.187 67.949,51.913 66.993,50.957 66.969,50.926 66.954,50.889 66.949,50.85 66.949,50.2 66.954,50.161 66.969,50.124 66.993,50.093 67.143,49.943 67.174,49.919 67.211,49.904 67.25,49.899 69.637,49.899 69.849,49.687 69.849,48.363 69.637,48.151 69.35,48.151 69.311,48.146 69.274,48.131 69.243,48.107 68.893,47.757 68.869,47.726 68.854,47.689 68.849,47.65 68.849,43.813 68.337,43.301 66.15,43.301 66.111,43.296 66.074,43.281 66.043,43.257 64.987,42.201 63.906,42.201 62.201,43.906 62.201,44.05 62.201,48.837 63.263,49.899 64.85,49.899 64.889,49.904 64.926,49.919 64.957,49.943 65.257,50.243 65.281,50.274 65.296,50.311 65.301,50.35 65.301,51.287 66.107,52.093 66.131,52.124 66.146,52.161 66.151,52.2 66.151,52.85 66.146,52.889 66.135,52.915 66.131,52.926 66.107,52.957 65.319,53.744 65.288,53.769 65.252,53.784 65.213,53.789 64.475,53.789 63.301,54.963 63.301,55.7 63.296,55.739 63.281,55.776 63.257,55.807 62.957,56.107 62.926,56.131 62.911,56.137 62.889,56.146 62.85,56.151 61.863,56.151 60.351,57.663 60.351,65.45 60.346,65.489 60.337,65.511 60.331,65.526 60.307,65.557 46.807,79.057 46.776,79.081 46.739,79.096 46.7,79.101 36.613,79.101 35.201,80.513 35.201,85.337 37.263,87.399 48.337,87.399
+12V on InternalPlane2 (split plane): 81.548,106.454 78.796,103.702 15.3,103.702 15.235,103.694 15.174,103.668 15.122,103.628 12.172,100.678 12.132,100.626 12.106,100.565 12.098,100.5 12.098,69.954 7.246,65.102 0.301,65.102 0.301,112.699 81.548,112.699
+2,5VCC on InternalPlane2 (split plane): 86.049,69.387 86.049,61.863 83.4,59.214 79.301,63.313 79.301,71.049 84.387,71.049
+2,5VETH on InternalPlane2 (split plane): 27.893,59.893 27.924,59.869 27.961,59.854 28,59.849 36.837,59.849 43.649,53.037 43.649,43.813 39.837,40.001 32,40.001 31.961,39.996 31.924,39.981 31.893,39.957 29.637,37.701 17.013,37.701 16.351,38.363 16.351,59.837 20.413,63.899 23.887,63.899
GND on InternalPlane2 (split plane): 40.824,51.712 40.824,46.888 40.187,46.251 35.738,46.251 35.176,46.813 35.176,51.412 36.213,52.449 40.087,52.449
GND on InternalPlane2 (split plane): 171.699,0.301 78.651,0.301 78.651,16.7 78.646,16.739 78.637,16.761 78.631,16.776 78.607,16.807 76.407,19.007 76.376,19.031 76.361,19.037 76.339,19.046 76.3,19.051 60,19.051 59.961,19.046 59.924,19.031 59.893,19.007 58.743,17.857 58.719,17.826 58.704,17.789 58.699,17.75 58.699,15.763 48.993,6.057 48.969,6.026 48.954,5.989 48.949,5.95 48.949,0.301 0.301,0.301 0.301,64.598 7.35,64.598 7.415,64.606 7.476,64.632 7.528,64.672 12.528,69.672 12.546,69.694 12.568,69.724 12.594,69.785 12.602,69.85 12.602,100.396 15.404,103.198 78.9,103.198 78.965,103.206 79.026,103.232 79.078,103.272 81.978,106.172 82.018,106.224 82.044,106.285 82.052,106.35 82.052,112.699 171.699,112.699
+3,3VLMS-1 on InternalPlane2 (split plane): 157.749,23.401 143.806,23.401 143.767,23.396 143.73,23.381 143.699,23.357 143.516,23.174 134.954,23.174 133.518,24.61 132.673,25.454 132.642,25.478 132.605,25.493 132.566,25.499 130.422,25.499 130.383,25.493 130.347,25.478 130.315,25.454 128.775,23.914 127.932,24.757 127.901,24.781 127.886,24.787 127.864,24.796 127.825,24.801 120.65,24.801 120.611,24.796 120.589,24.787 120.574,24.781 120.543,24.757 119.443,23.657 119.419,23.626 119.404,23.589 119.399,23.55 119.399,15.082 118.316,15.082 118.277,15.077 118.24,15.062 118.209,15.037 116.433,13.262 116.409,13.23 116.394,13.194 116.389,13.155 116.389,10.989 116.394,10.949 116.409,10.913 116.433,10.882 117.323,9.992 117.32,9.971 117.325,9.932 117.34,9.895 117.364,9.864 117.396,9.84 117.432,9.825 117.471,9.82 121.153,9.82 121.192,9.825 121.229,9.84 121.26,9.864 122.753,11.357 126.957,11.357 126.996,11.363 127.033,11.378 127.064,11.402 128.832,13.17 130.436,13.17 130.475,13.175 130.512,13.19 130.543,13.214 132.328,14.999 135.822,14.999 135.822,13.394 135.822,6.051 115.845,6.051 114.981,6.915 114.981,23.401 122.602,31.022 144.196,31.022 144.235,31.027 144.271,31.042 144.303,31.066 144.736,31.499 157.749,31.499
+2,5VFPGA on InternalPlane2 (split plane): 165 vertices, not listed, extent 24.164,25.151 88.749,80.299
+2,5VRAM on InternalPlane2 (split plane): 78.349,16.637 78.349,0.301 49.251,0.301 49.251,5.887 58.957,15.593 58.981,15.624 58.996,15.661 59.001,15.7 59.001,17.687 60.063,18.749 76.237,18.749

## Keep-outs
Keep-Out Layer:
  the board outline again, w0.2

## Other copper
Top Layer:
  region net +3,0VCC: 103.55,104.15 103.55,112.54 90.75,112.54 90.75,104.15
  region net +5V: 112.8,91.4 104.41,91.4 104.41,77.3 112.8,77.3
  region net +3,3VLMS-1: 157.55,31.387 150.36,31.387 150.36,23.5 157.55,23.5
  region net +1,8VDLMS-1: 157.55,23.001 150.36,23.001 150.36,14.9 157.55,14.9
  region net +1,8VALMS-1: 157.5,40.13 150.31,40.13 150.31,31.9 157.5,31.9
  region net +2,5VLMS-1: 157.55,14.255 150.36,14.255 150.36,6.2 157.55,6.2
  region net +2,5VLMS-2: 157.5,63.9 150.31,63.9 150.31,55.845 157.5,55.845
  region net +1,8VDLMS-2: 157.5,72.5 150.31,72.5 150.31,64.399 157.5,64.399
  region net +3,3VLMS-2: 157.5,80.75 150.31,80.75 150.31,72.863 157.5,72.863
  region net +1,8VALMS-2: 157.51,89.324 150.32,89.324 150.32,81.094 157.51,81.094
  rectangle net GND: 124.65,72.4 125.35,73.5
  text "Fairwaves" at 87.85,30 h2
  text "UmTRX" at 86.8,25.8 h1.75
  text "v0.1a" at 96.55,25.8 h1.75
  text ".Print_Date" at 93.25,21.95 h1.52
  text "CC-BY-SA 3.0" at 85.85,17.65 h2
Bottom Layer:
  rectangle net GND: 4.8,98.425 81.55,103.275
InternalPlane2 (plane layer: these items are gaps in the copper):
  lines w0.3: 24.057,64.157 24.057,72.757 31.75,80.45 35.05,80.45 ; 29.761,37.413 29.761,35.289 31.8,33.25 73.85,33.25 82.1,25 84.25,25 88.9,29.65 88.9,47.75 86.45,50.2 86.45,54.85 86.45,55.95 ; 49.1,0.05 49.1,5.95 58.85,15.7 58.85,17.75 60,18.9 76.3,18.9 78.5,16.7 78.5,0.05 ; 79.15,71.2 84.45,71.2 86.2,69.45 86.2,61.8 83.4,59 ; 86.4,56 79.15,63.25 79.15,71.55 78.1,72.6 69.75,72.6 66.55,69.4 ; 117.488,59.371 116.579,60.28 116.579,62.004 118.797,64.222 127.408,64.222 128.144,64.959 128.144,73.644 ; 117.51,59.263 119.849,59.263 121.192,59.263 122.73,60.8 126.996,60.8 128.808,62.613 130.475,62.613 132.931,65.069 132.931,65.569 132.931,66.181 133.6,66.85 135.065,66.85 136.807,65.108 136.807,64.1 144.132,64.1 144.339,63.893 145.404,63.893 ; 119.55,15 119.55,23.55 120.65,24.65 127.825,24.65 128.775,23.7 ; 119.85,64.2 119.85,73.175 120.319,73.644 128.144,73.644 ; 131.674,80.508 131.674,87.525 134.012,89.864 157.736,89.864 158.35,89.25 158.35,80.85 ; 135.974,15.126 135.974,13.394 ; 136.013,55.201 136.013,62.686 136.807,63.48 136.807,64.306 ; 145.469,63.85 158.1,63.85 158.35,63.85 ; 157.9,14.5 146.45,14.5 145.8,15.15 135.95,15.15 132.265,15.15 130.436,13.321 ; 157.9,23.25 143.806,23.25 143.578,23.022 135.417,23.022 134.891,23.022 133.411,24.503 ; 35.05,80.45 36.55,78.95 46.7,78.95 60.2,65.45 60.2,57.6 61.8,56 62.85,56 63.15,55.7 63.15,54.9 64.413,53.637 65.213,53.637 66,52.85 66,52.2 65.15,51.35 65.15,50.35 64.85,50.05 63.2,50.05 62.05,48.9 62.05,44.05 62.05,43.843 63.843,42.05 65.05,42.05 66.15,43.15 68.4,43.15 69,43.75 69,47.65 ; 35.05,80.45 35.05,85.4 37.2,87.55 48.4,87.55 66.55,69.4 ; 66.55,69.4 66.55,56.65 66.05,56.15 66.05,55.3 68.1,53.25 68.1,51.85 67.1,50.85 67.1,50.2 67.25,50.05 68.7,50.05 69.7,50.05 70,49.75 70,48.3 69.7,48 69.35,48 69,47.65 ; 69,47.65 69,47.65 ; 114.829,6.853 115.782,5.9 ; 114.829,6.853 114.829,23.463 ; 114.829,6.853 114.829,23.463 ; 114.829,6.853 115.782,5.9 ; 114.829,23.463 122.539,31.173 ; 114.829,23.463 122.539,31.173 ; 115.782,5.9 127.585,5.9 ; 115.782,5.9 127.585,5.9 ; 116.54,10.989 116.54,13.155 ; 116.54,10.989 117.449,10.079 116.54,10.989 ; 116.54,10.989 116.54,13.155 ; 116.54,13.155 118.316,14.93 ; 116.54,13.155 118.316,14.93 ; 118.316,14.93 127.369,14.93 ; 118.316,14.93 127.369,14.93 ; 119.81,9.971 117.471,9.971 119.81,9.971 ; 119.81,9.971 121.153,9.971 ; 119.81,9.971 121.153,9.971 ; 121.153,9.971 122.691,11.509 ; 121.153,9.971 122.691,11.509 ; 122.539,31.173 143.806,31.173 ; 122.539,31.173 143.806,31.173 ; 122.691,11.509 126.957,11.509 ; 122.691,11.509 126.957,11.509 ; 126.957,11.509 128.769,13.321 ; 126.957,11.509 128.769,13.321 ; 127.369,14.93 128.105,15.667 ; 127.369,14.93 128.105,15.667 ; 127.585,5.9 144.261,5.9 ; 127.585,5.9 144.261,5.9 ; 128.105,15.667 128.105,23.03 ; 128.105,15.667 128.105,23.03 ; 128.105,23.03 130.422,25.347 ; 128.105,23.03 130.422,25.347 ; 128.144,73.644 129.139,74.639 132.605,74.639 133.3,73.944 133.3,72.55 133.137,72.387 132.389,72.387 132.129,72.127 132.129,70.921 132.6,70.45 135.35,70.45 137.214,72.314 145.464,72.314 150.114,72.314 150.35,72.55 158.35,72.55 ; 128.769,13.321 130.436,13.321 ; 128.769,13.321 130.436,13.321 ; 130.422,25.347 132.566,25.347 ; 130.422,25.347 132.566,25.347 ; 131.635,38.234 133.973,40.572 ; 131.635,38.234 131.635,31.216 131.635,38.234 ; 131.635,38.234 133.973,40.572 ; 132.566,25.347 133.411,24.503 ; 132.566,25.347 133.411,24.503 ; 133.973,40.572 144.542,40.572 ; 133.973,40.572 144.542,40.572 ; 135.974,13.394 135.974,5.91 135.974,13.394 ; 143.806,31.173 144.196,31.173 ; 143.806,31.173 144.196,31.173 ; 144.196,31.173 144.673,31.65 157.9,31.65 ; 144.261,5.9 157.15,5.9 157.9,6.65 157.9,31.65 ; 144.542,40.572 157.128,40.572 157.9,39.8 157.9,31.65 ; 158.35,63.85 158.35,56.25 157.291,55.191 145.469,55.191 127.624,55.191 115.821,55.191 114.868,56.144 114.868,72.755 122.578,80.465 143.845,80.465 148.065,80.465 148.45,80.85 158.35,80.85 ; 158.35,63.85 158.35,72.55 ; 158.35,72.55 158.35,80.85 ; 16.2,38.3 16.2,59.9 20.35,64.05 23.95,64.05 28,60 32.65,60 36.9,60 43.8,53.1 43.8,43.75 39.9,39.85 32,39.85 29.7,37.55 16.95,37.55 16.2,38.3 ; 35.025,46.75 35.025,51.475 36.15,52.6 40.15,52.6 40.975,51.775 40.975,46.825 40.25,46.1 35.675,46.1 35.025,46.75
  lines w0.5: -0.3,64.85 7.35,64.85 12.35,69.85 12.35,100.5 15.3,103.45 78.9,103.45 81.8,106.35 81.8,112.9

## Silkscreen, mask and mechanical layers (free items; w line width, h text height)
Top Overlay:
  text "F1" at 91,103.8 h1.52
  text "GPS" at 161.6,100.4 h1.52 r270
  text "CLOCK" at 161.3,90.1 h1.52 r270
  text "FAN2" at 99.9,89.4 h1.52
  text "MASTR" at 160.8,78.5 h1.52
  text "SLAVE" at 160.9,75.6 h1.52
  text "MHZ" at 163.9,70.2 h1.52
  text "1PPS" at 162.9,67.4 h1.52
  text "SAFE" at 161.4,63.6 h1.52 r270
  text "MISO2" at 96.6,55.5 h1
  text "SCLK2" at 96.4,53.9 h1
  text "RST" at 161.6,53 h1.52 r270
  text "MOSI2" at 96.5,52.4 h1
  text "SEN2" at 97.3,50.9 h1
  text "TX2" at 104.3,50.6 h1.52 r270
  text "LNA-D" at 161.4,45.4 h1.52 r270
  text "LNA" at 161.4,32.6 h1.52 r270
  text "MISO1" at 97.2,14.5 h1
  text "SCLK1" at 97.1,12.9 h1
  text "MOSI1" at 97.2,11.4 h1
  text "TX1" at 103.3,10.3 h1.52 r270
  text "SEN1" at 98,9.8 h1
Top Solder:
  circle w0.254: c62.25,59.85 r0.15
  circle w0.254: c61.7,59.5 r0.15
  circle w0.254: c81.7,63.225 r0.15
  circle w0.254: c82.2,62.7 r0.15
  circle w0.254: c87.35,37.45 r0.15
  circle w0.254: c92.2,42.8 r0.15
  circle w0.254: c91.4,42.85 r0.15
  circle w0.254: c90.65,42.95 r0.15
  circle w0.254: c92.75,49 r0.15
  circle w0.254: c90.15,50.7 r0.15
  circle w0.254: c89.25,50.5 r0.15
  circle w0.254: c88.45,50.7 r0.15
  circle w0.254: c87.6,51.75 r0.15
  circle w0.254: c85.75,52.6 r0.15
  circle w0.254: c85.192,52.608 r0.15
  circle w0.254: c84.6,52.65 r0.15
  circle w0.254: c83.95,52.5 r0.15
  circle w0.254: c82.3,53.35 r0.15
  circle w0.254: c82.15,53.95 r0.15
  circle w0.254: c81.85,54.5 r0.15
  circle w0.254: c81.35,54.95 r0.15
  circle w0.254: c86.5,37.55 r0.15
  circle w0.254: c86.15,37.05 r0.15
  circle w0.254: c98.625,48.2 r0.15
  circle w0.254: c85.35,62.55 r0.15
  circle w0.254: c83.2,60 r0.15
  circle w0.254: c77.4,56.7 r0.15
  circle w0.254: c81.8,55.45 r0.15
  circle w0.254: c80.525,54.975 r0.15
  circle w0.254: c93.55,49.1 r0.15
  circle w0.254: c93.95,45.95 r0.15
  circle w0.254: c94.9,45.9 r0.15
  circle w0.254: c100.5,45.05 r0.15
  circle w0.254: c99.823,45.06 r0.15
  circle w0.254: c102.45,47.1 r0.15
  circle w0.254: c101.793,47.13 r0.15
  circle w0.254: c111.95,57.95 r0.15
  circle w0.254: c112.7,57.2 r0.15
  circle w0.254: c111.9,57.35 r0.15
  circle w0.254: c111.45,57 r0.15
  region: 84,112.65 83,112.65 83,74.8 84,74.8
  region: 84,74.8 84,75.8 0.3,75.8 0.3,74.8
  rectangle: 113.65,4.7 114.65,90.95
  rectangle: 134.75,54.55 135.75,90.8
  rectangle: 158.25,4.7 159.2,91.05
  rectangle: 134.75,5.05 135.65,41.2
  rectangle: 114.05,4.65 159.05,5.75
  rectangle: 113.5,40.75 159.05,41.7
  rectangle: 113.6,53.95 158.85,55.1
  rectangle: 113.6,90.05 159.2,91.05
  region: 1.3,112.65 0.3,112.65 0.3,74.8 1.3,74.8
  region: 84.05,111.6 84.05,112.6 0.35,112.6 0.35,111.6
  text "Fairwaves" at 87.85,30 h2
  text "UmTRX" at 86.8,25.8 h1.75
  text "v0.1a" at 96.55,25.8 h1.75
  text ".Print_Date" at 93.25,21.95 h1.52
  text "CC-BY-SA 3.0" at 85.85,17.65 h2
Bottom Solder:
  rectangle: 4.65,98.45 81.4,103.3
